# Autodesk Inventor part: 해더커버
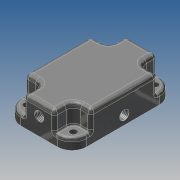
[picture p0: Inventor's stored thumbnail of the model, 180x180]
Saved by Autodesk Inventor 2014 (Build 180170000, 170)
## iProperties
Company: 한국ATC센터
Created: 2014-01
Part Number: 해더커버
Document SubType Name: Modeling
Designer: KYOUNG IL JANG
Density: 1 g/cm^3
Material: 알루미늄 6061
Mass: 46.0999 g
Surface Area: 123.575 cm^2
Volume: 46.0999 cm^3
Vendor: CBT Solutions
Appearance: 매끄러움 - 중간 회색
Author: KYOUNG IL JANG
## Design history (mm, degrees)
sketch "스케치1"
  geometry: L1 (22.5, -32)-(22.5, 25) reference; L2 (-19.5, -35)-(19.5, -35) reference; L3 (-22.5, 25)-(-22.5, -32) reference; L4 (12.5, 35)-(-12.5, 35) reference; A1 r 10 centre (12.5, 25) between (22.5, 25) and (12.5, 35) reference; A2 r 3 centre (19.5, -32) between (19.5, -35) and (22.5, -32) reference; A3 r 3 centre (-19.5, -32) between (-22.5, -32) and (-19.5, -35) reference; A4 r 10 centre (-12.5, 25) between (-12.5, 35) and (-22.5, 25) reference; 1 further point
extrude "돌출1" new body sketch "스케치1" distance "d0" = 20; taper "d1" = 0 deg
extrude "돌출2" cut sketch "스케치2" distance "d5" = 13; taper "d6" = 0 deg
fillet "모깎기1" dims "d7" = 5
fillet "모깎기2" dims "d8" = 1
fillet "모깎기3" dims "d9" = 2
fillet "모깎기4" dims "d10" = 3
sketch "스케치3"
  geometry: L1 (-21.5, -1)-(-8.5, -1) reference; L2 (10.5, -1)-(23.5, -1) reference; L3 (-32, 0)-(25, 0) reference; L4 (-15, -1)-(-15, 0); L5 (17, -1)-(17, 0); L6 (-2.75, 0)-(-2.75, 7); L7 (-15, 7)-(-2.75, 7); L8 (-15, 0)-(-15, 7); L9 (17, 0)-(17, 7); L10 (4.75, 0)-(4.75, 7); L11 (4.75, 7)-(17, 7); 1 further point
  constraints: 16 end point, 7 parallel, 4 perpendicular, 4 point on line, 2 midpoint, 1 horizontal alignment
  dimensions: "d11" = 8 distance of L5.start L9.end; "d12" = 24.5 diameter of L6 L8; "d13" = 24.5 diameter of L10 L9 (= d12)
  node "참조15"
  node "참조16"
  node "참조17"
revolve "회전1" stored, may be unused: angle "d14" = 90 deg
revolve "회전2" stored, may be unused: angle "d15" = 90 deg
fillet "모깎기5" dims "d16" = 5
sketch "스케치4"
  geometry: C1 r 2.229 at (16, -27.5) reference; C2 r 2.229 at (16, 28.5) reference; C3 r 2.229 at (-16, -27.5) reference; C4 r 2.229 at (-16, 28.5) reference; 1 further point
hole "구멍1" sketch "스케치4" at (16, -27.5), (-16, -27.5), (16, 28.5), (-16, 28.5) diameter "d17" = 4.5; stored, may be unused: countersink angle "d21" = 90 deg, drill point angle "d23" = 118 deg; dims "d18" = 6, "d19" = 4, "d20" = 2, "d22" = 8
sketch "스케치5"
  geometry: L1 (-20.09, 3.496)-(-22.691, 8); L2 (-29.619, 12)-(-37.219, 12); L3 (-35, 0)-(-32, 0) reference; L4 (-35, 8)-(-35, 17) reference; L5 (36.506, 12)-(30.619, 12); L6 (23.691, 8)-(20.656, 2.744); L7 (35, 17)-(35, 8) reference; A1 r 8 centre (-29.619, 4) between (-22.691, 8) and (-29.619, 12); A2 r 8 centre (30.619, 4) between (30.619, 12) and (23.691, 8); 5 further points
  constraints: 8 end point, 8 point on line, 4 point on circle, 4 tangent, 2 centre point, 1 collinear, 1 horizontal, 1 perpendicular
  dimensions: "d24" = 12 distance between parallel lines of L2 L3; "d25" = 10 distance from line of point (-25, 12) L4; "d26" = 120 deg angle of L1 L2; "d27" = 8 radius of A1; "d29" = 9 distance from line of point (26, 12) L7; "d30" = 120 deg angle of L6 L5; "d31" = 8 radius of A2
node "작업점1"
node "작업점2"
hole "구멍2" diameter "d34" = 5.944; stored, may be unused: countersink angle "d40" = 90 deg, drill point angle "d42" = 0 deg; dims "d32" = 10, "d33" = 10, "d35" = 6.886, "d36" = 0.62479, "d37" = 5.959, "d38" = 4, "d39" = 2, "d41" = 6.9
hole "구멍3" diameter "d45" = 5.944; stored, may be unused: countersink angle "d51" = 90 deg, drill point angle "d53" = 0 deg; dims "d43" = 10, "d44" = 10, "d46" = 6.886, "d47" = 0.62479, "d48" = 5.959, "d49" = 4, "d50" = 2, "d52" = 6.9
sketch "스케치6"
  geometry: C1 r 2.972 at (19.5, 12) reference; 1 further point
feature "스윕1" sketch "스케치6" dims "d54" = 0
sketch "스케치7"
  geometry: C1 r 2.972 at (12.5, -12) reference; 1 further point
feature "스윕2" sketch "스케치7" dims "d55" = 0
sketch "스케치8"
  geometry: L1 (0, 36.75)-(0, 61.25) reference; L2 (0, 4.75)-(0, 29.25) reference; L3 (0, 36.75)-(0, 29.25); 3 further points
  constraints: 2 end point, 1 collinear, 1 horizontal alignment, 1 midpoint
  dimensions: "d57" = 6 distance of point (6, 33) point (0, 33)
hole "구멍4" sketch "스케치8" at (6, 33) diameter "d58" = 5.944; stored, may be unused: countersink angle "d64" = 90 deg, drill point angle "d66" = 0 deg; dims "d59" = 6.886, "d60" = 0.62479, "d61" = 5.959, "d62" = 4, "d63" = 2, "d65" = 6.9
sketch "스케치10"
  geometry: C1 r 2.972 at (0, 0) reference; 1 further point
  node "투영된 루프4"
sketch "스케치11"
  geometry: C1 r 2.972 at (0, 0) reference; 1 further point
  node "투영된 루프5"
node "작업축3"
node "작업 평면2"
sketch "스케치12"
  geometry: L1 (3.443, -2.979)-(3.443, 2.98) reference; L2 (3.443, 0)-(11.057, 0); L3 (19.057, -8)-(19.057, -11.414); A1 r 8 centre (11.057, -8) between (19.057, -8) and (11.057, 0); 2 further points
  constraints: 4 end point, 2 perpendicular, 2 point on circle, 2 point on line, 2 tangent, 1 centre point, 1 midpoint, 1 vertical alignment
  dimensions: "d70" = 8 radius of A1
feature "스윕3" sketch "스케치12" dims "d71" = 0
node "작업 평면3"
sketch "스케치13"
  geometry: L1 (34.657, -2.972)-(34.657, 2.972) reference; L2 (34.657, 0)-(27.057, 0); L3 (19.057, 8)-(19.057, 10.673); A1 r 8 centre (27.057, 8) between (19.057, 8) and (27.057, 0); 1 further point
  constraints: 4 end point, 2 perpendicular, 2 point on circle, 2 tangent, 1 centre point, 1 midpoint, 1 point on line
  dimensions: "d73" = 8 radius of A1
feature "스윕4" sketch "스케치13" dims "d74" = 0
feature "면 삭제1"
fillet "모깎기6" dims "d75" = 10
node "솔리드1"
mirror "대칭1"
node "참조1"
node "참조2"
node "참조3"
node "참조4"
node "참조5"
node "참조6"
node "참조7"
node "참조8"
node "참조18"
node "참조19"
node "참조20"
node "참조21"
node "투영된 루프2"
node "투영된 루프3"
other parameters: "d2" = 12, "d3" = 5.5 (derived), "d4" = 5.5, "d69" = -15 deg, "d72" = 15 deg
